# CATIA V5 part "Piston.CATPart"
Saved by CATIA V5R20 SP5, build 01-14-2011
Part number: Piston
Bounding box of the stored display mesh (mm): x -40 to 60, y -350 to 0, z -40 to 40
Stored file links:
  M:\EU_thinkMotion\IAO_2010\iao\IAO_MMS_Groupe2\IAO_MMS_Groupe2\rwatrin\rwatrin\Piston.CATPart
  M:\EU_thinkMotion\IAO_2010\iao\IAO_MMS_Groupe2\IAO_MMS_Groupe2\rwatrin\rwatrin\mecanisme_iao_optimise.CATProduct
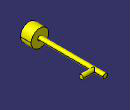
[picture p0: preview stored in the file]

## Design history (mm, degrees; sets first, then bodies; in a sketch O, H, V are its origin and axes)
Parameters
  `Longueur_tige_vérin` = 300 mm
Set1
  DatumSurface1: linked copy from another document
  Sketch1, origin (25, -234.2404, 186.5709), H (0, 0.7671, 0.6415), V (0, -0.6415, 0.7671), geometry linked from another document
Set2
  Point1: type OnCurve, Support Sketch1, Length 0
  Point2: (45, -50, 0)
Body1 (main body)
  Sketch2 on zx-plane, origin (0, 0, 0), H (-1, 0, 0), V (0, 0, 1)
    circle A1 centre (0, 0) radius 10
    point P1 (10, 0)
    radius A1 = 10
    coincidence: A1 P1, P1 H
  Pad1: profile Sketch2, direction (0, -1, 0), length 300
  Sketch3 on end face of Pad1, origin (0, -300, 0), H (1, 0, 0), V (0, 0, 1)
    circle A1 centre (0, 0) radius 40
    point P1 (40, 0)
    radius A1 = 40
    coincidence: A1 P1, P1 H
  Pad2: profile Sketch3, direction (0, -1, 0), length 50
  Sketch4 on yz-plane, origin (0, 0, 0), H (0, 1, 0), V (0, 0, 1)
    circle A1 centre (-50, 0) radius 10
    point P1 (-50, 0)
    reference projected line E1 (-350, -25) -> (-350, 25) from edge [face of Pad2 from Sketch3.A1 | end face of Pad2]
    radius A1 = 10
    distance P1 E1 = 300 {= `Longueur_tige_vérin`}
    coincidence: P1 H
  Pad3: profile Sketch4, direction (1, 0, 0), length 60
